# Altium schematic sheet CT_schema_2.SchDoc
size 339 x 183 mm
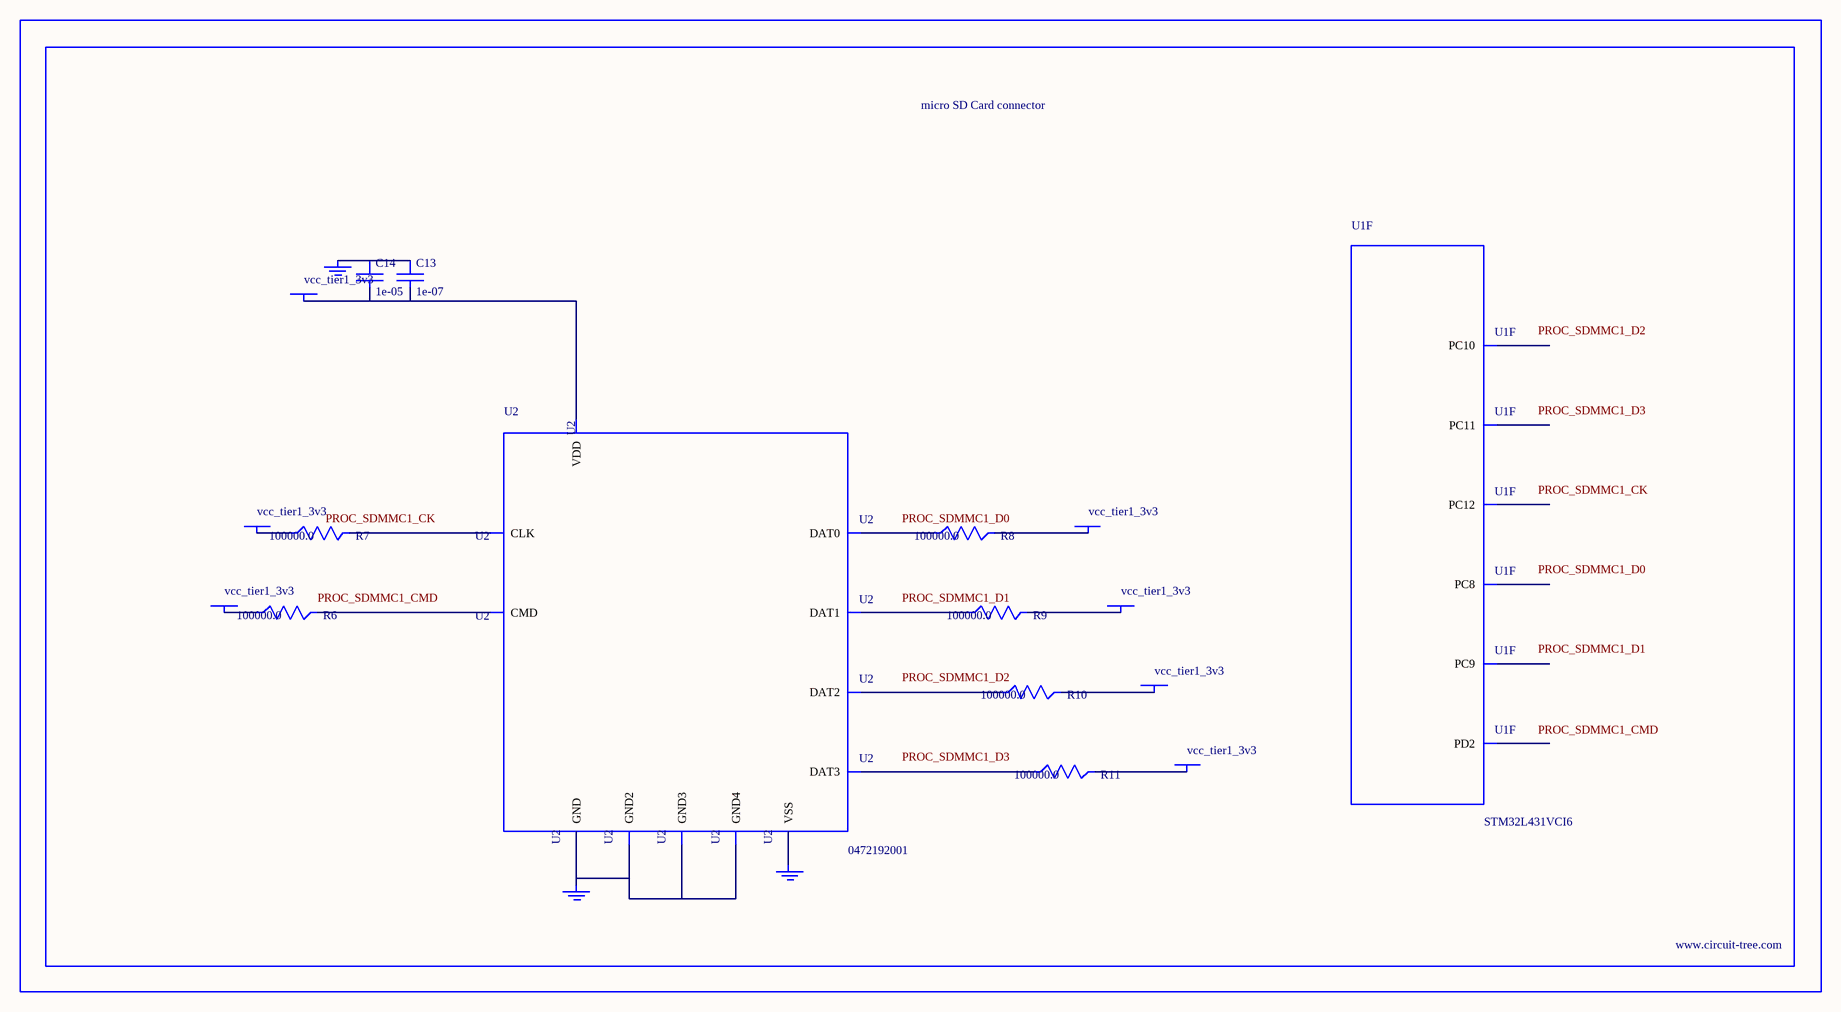
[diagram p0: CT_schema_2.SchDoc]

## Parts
BORDER1  (no value)
C13  1e-07  [C0402]
C14  1e-05  [C0805]
GND_INSTANCE_1_0  (no value)
GND_INSTANCE_1_1  (no value)
GND_INSTANCE_1_2  (no value)
POWER_INSTANCE_1_0  vcc_tier1_3v3
POWER_INSTANCE_1_1  vcc_tier1_3v3
POWER_INSTANCE_1_2  vcc_tier1_3v3
POWER_INSTANCE_1_3  vcc_tier1_3v3
POWER_INSTANCE_1_4  vcc_tier1_3v3
POWER_INSTANCE_1_5  vcc_tier1_3v3
POWER_INSTANCE_1_6  vcc_tier1_3v3
R6  100000.0  [R0603]
R7  100000.0  [R0603]
R8  100000.0  [R0603]
R9  100000.0  [R0603]
R10  100000.0  [R0603]
R11  100000.0  [R0603]
U1  STM32L431VCI6  [UFBGA100]  (part F of 9)
U2  0472192001  [MOLEX_47219-2001]

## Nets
NetC13_1: C13.1 C14.1 GND_INSTANCE_1_0.0(GND)
NetC13_2: C13.2 C14.2 POWER_INSTANCE_1_3.0(PWR) U2.4(VDD)
NetGND_INSTANCE_1_1_0: GND_INSTANCE_1_1.0(GND) U2.6(VSS)
NetGND_INSTANCE_1_2_0: GND_INSTANCE_1_2.0(GND) U2.G1(GND) U2.G2(GND2) U2.G3(GND3) U2.G4(GND4)
NetPOWER_INSTANCE_1_0_0: POWER_INSTANCE_1_0.0(PWR) R10.2
NetPOWER_INSTANCE_1_1_0: POWER_INSTANCE_1_1.0(PWR) R11.2
NetPOWER_INSTANCE_1_2_0: POWER_INSTANCE_1_2.0(PWR) R6.1
NetPOWER_INSTANCE_1_4_0: POWER_INSTANCE_1_4.0(PWR) R7.1
NetPOWER_INSTANCE_1_5_0: POWER_INSTANCE_1_5.0(PWR) R8.2
NetPOWER_INSTANCE_1_6_0: POWER_INSTANCE_1_6.0(PWR) R9.2
NetR6_2: R6.2 U2.3(CMD)
NetR7_2: R7.2 U2.5(CLK)
NetR8_1: R8.1 U2.7(DAT0)
NetR9_1: R9.1 U2.8(DAT1)
NetR10_1: R10.1 U2.1(DAT2)
NetR11_1: R11.1 U2.2(DAT3)

Not connected (* = marked no-connect by the designer): U1 B10(PC12) B11(PC10) C8(PD2) C10(PC11) D12(PC9) E10(PC8)

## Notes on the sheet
- Labels drawn without touching a wire or pin: PROC_SDMMC1_CK, PROC_SDMMC1_CMD, PROC_SDMMC1_D0, PROC_SDMMC1_D1, PROC_SDMMC1_D2, PROC_SDMMC1_D3

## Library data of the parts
BORDER1 = BORDER_PAGE1
C13 = C0402C104K3RACTU
C14 = C0805C106K8RACTU
GND_INSTANCE_1_0-GND_INSTANCE_1_2 = GND
POWER_INSTANCE_1_0-POWER_INSTANCE_1_6 = PWR
R6-R11 = RC0603JR-07100KL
